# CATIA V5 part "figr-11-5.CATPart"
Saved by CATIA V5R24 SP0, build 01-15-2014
Part number: Part4
Bounding box of the stored display mesh (mm): x -40 to 40, y -90 to 150, z -30.056 to 96
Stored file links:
  D:\KAVITA\CATIA V5-6R2014 Project_ Kavita\CATIA V5-6R2014_partfiles\Partfiles\c11_catia_v5-6r2014_prt\figr-11-5.CATPart
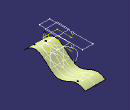
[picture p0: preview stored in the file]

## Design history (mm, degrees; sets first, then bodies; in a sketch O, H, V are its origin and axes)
Body1 (main body)
  Sketch1 on yz-plane, origin (0, 0, 0), H (0, 1, 0), V (0, 0, 1)
    spline S1 through (-90, 0) (-30, 20) (50, -30) (110, -10) (150, -20)
  Extrude1: Element1 Sketch1, Lim1 40, Lim2 40
  Plane1: type Offset, RefPlane xy-plane, Offset 50
  Sketch2 on Plane1, origin (0, 0, 50), H (1, 0, 0), V (0, 1, 0)
    spline S1 through (30, 100) (-10, 40) (20, -10) (-10, -60)
  Plane2: type Offset, RefPlane Plane1, Offset 46
  Sketch3 on Plane2, origin (0, 0, 96), H (1, 0, 0), V (0, 1, 0)
    line L1 (-20, 120) -> (20, 120)
    line L2 (20, 120) -> (20, -50)
    line L3 (20, -50) -> (-20, -50)
    line L4 (-20, -50) -> (-20, 120)
    horizontal: L1 H, L3 H
    vertical: L2 V, L4 V
  MultiSel1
